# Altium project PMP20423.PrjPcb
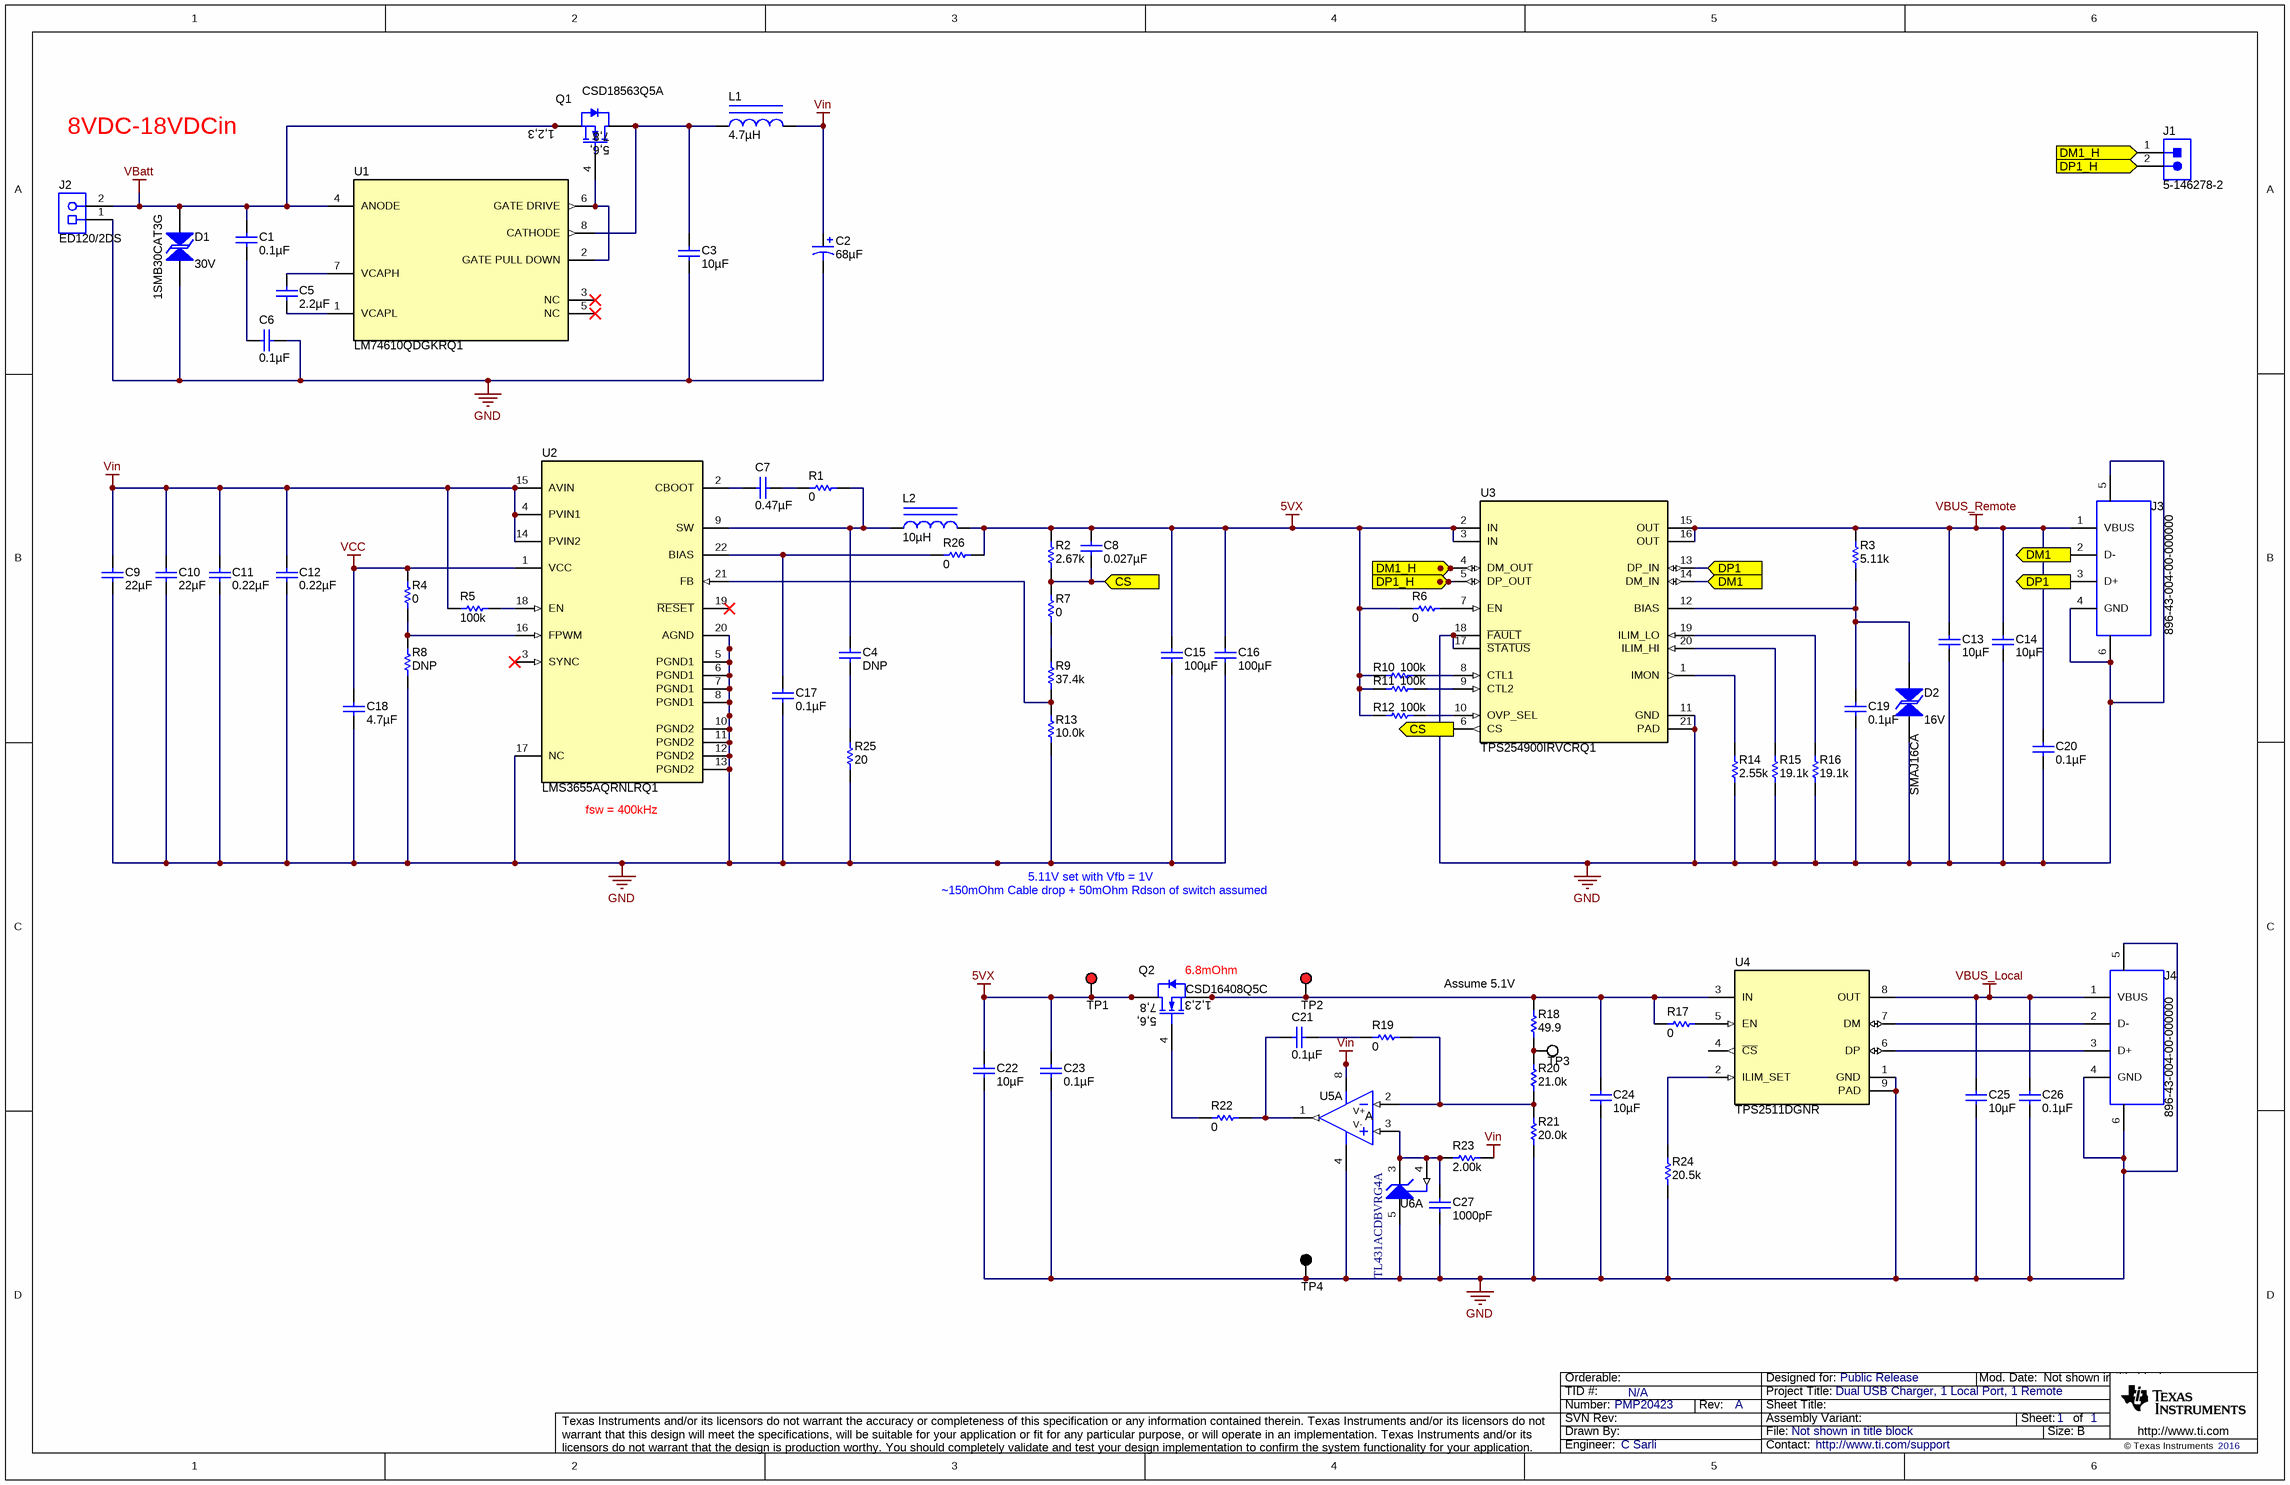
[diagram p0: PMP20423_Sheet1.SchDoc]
CopyrightYear: 2016; PCB_Layout: C Sarli; PCB_Rev: A; PRJ_Customer: Public Release; PRJ_Engineer: C Sarli; PRJ_Number: PMP20423; PRJ_Title: Dual USB Charger, 1 Local Port, 1 Remote; SCH_Rev: A; TechSupport: http://www.ti.com/support; TID: N/A
1 sheet, 73 parts. Net scope: flat (ports and power ports of the same name join across sheets).
Board file: PMP20423.PcbDoc

## Sheet PMP20423_Sheet1.SchDoc
size 431 x 279 mm; Date: Not shown in title block; ApprovedBy: Not shown in title block; CheckedBy: Not shown in title block; Author: Not shown in title block; CompanyName: Not shown in title block; Engineer: Not shown in title block; Organization: Not shown in title block; Address1: Not shown in title block; Address2: Not shown in title block; Address3: Not shown in title block; Address4: Not shown in title block; DocumentNumber: 1; Revision: Use project parameter SCH_Rev; SheetNumber: 1; SheetTotal: 1; PageSetup: Record=PageOptions¦CenterHorizontal=True¦CenterVertical=True¦PrintScale=1.00¦XCorrection=1.00¦YCorrection=1.00¦PrintKind=0¦BorderSize=5000000¦LeftOffset=0¦BottomOffset=0¦Orientation=2¦PaperLength=1000¦PaperWidth=1000¦Scale=100¦PaperSource=15¦PrintQuality=600¦MediaType=1¦DitherType=10¦PaperKind=Letter¦PrintScaleMode=1

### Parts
C1  ValueDisplayed: 0.1µF  [0402]  (hidden comment: C1005X7R1H104K050BB)
C2  ValueDisplayed: 68µF  [SM_RADIAL_D8]  (hidden comment: EEE-FK1V680XP)
C3  ValueDisplayed: 10µF  [1206_180]  (hidden comment: GRM31CR61H106KA12L)
C4  ValueDisplayed: DNP  [0402L]  (hidden comment: GRM155R71H331KA01D)
C5  ValueDisplayed: 2.2µF  [0603]  (hidden comment: GRM188R61A225KE34D)
C6  ValueDisplayed: 0.1µF  [0402]  (hidden comment: C1005X7R1H104K050BB)
C7  ValueDisplayed: 0.47µF  [0603L]  (hidden comment: GRM188R71E474KA12D)
C8  ValueDisplayed: 0.027µF  [0402L]  (hidden comment: GRM155R61C273KA01D)
C9  ValueDisplayed: 22µF  [1812_280L]  (hidden comment: C4532X7R1E226M250KC)
C10  ValueDisplayed: 22µF  [1812_280L]  (hidden comment: C4532X7R1E226M250KC)
C11  ValueDisplayed: 0.22µF  [0603L]  (hidden comment: C1608X7R1H224K080AB)
C12  ValueDisplayed: 0.22µF  [0603L]  (hidden comment: C1608X7R1H224K080AB)
C13  ValueDisplayed: 10µF  [0805_HV]  (hidden comment: GCM21BR70J106KE22L)
C14  ValueDisplayed: 10µF  [0805_HV]  (hidden comment: GCM21BR70J106KE22L)
C15  ValueDisplayed: 100µF  [1210_270L]  (hidden comment: GRM32ER61A107ME20L)
C16  ValueDisplayed: 100µF  [1210_270L]  (hidden comment: GRM32ER61A107ME20L)
C17  ValueDisplayed: 0.1µF  [0402L]  (hidden comment: C1005X7R1H104K050BB)
C18  ValueDisplayed: 4.7µF  [0603L]  (hidden comment: GRM188Z71C475KE21D)
C19  ValueDisplayed: 0.1µF  [0402L]  (hidden comment: C1005X7R1H104K050BB)
C20  ValueDisplayed: 0.1µF  [0402L]  (hidden comment: C1005X7R1H104K050BB)
C21  ValueDisplayed: 0.1µF  [0402L]  (hidden comment: C1005X7R1H104K050BB)
C22  ValueDisplayed: 10µF  [0805_HV]  (hidden comment: GRM21BR61C106KE15L)
C23  ValueDisplayed: 0.1µF  [0402L]  (hidden comment: C1005X7R1H104K050BB)
C24  ValueDisplayed: 10µF  [0805_HV]  (hidden comment: GRM21BR61C106KE15L)
C25  ValueDisplayed: 10µF  [0805_HV]  (hidden comment: GCM21BR70J106KE22L)
C26  ValueDisplayed: 0.1µF  [0402L]  (hidden comment: C1005X7R1H104K050BB)
C27  ValueDisplayed: 1000pF  [0402L]  (hidden comment: GRM155R61H102KA01D)
D1  1SMB30CAT3G  value 30V  [SMB-Bi]
D2  SMAJ16CA  value 16V  [SMA]
J1  5-146278-2  [TE_5-146278-2]
J2  ED120/2DS  [On-Shore_ED120_2DS]
J3  896-43-004-00-000000  [CONN_USB_896-43-004-00-000000]
J4  896-43-004-00-000000  [CONN_USB_896-43-004-00-000000]
L1  ValueDisplayed: 4.7µH  [XAL5030]  (hidden comment: XAL5030-472MEB)
L2  ValueDisplayed: 10µH  [MSS1278]  (hidden comment: MSS1278-103MLB)
Q1  CSD18563Q5A  [DQJ0008A]
Q2  CSD16408Q5C  [TRANS_NexFET_Q5C]
R1  ValueDisplayed: 0  [0402L]  (hidden comment: CRCW04020000Z0ED)
R2  ValueDisplayed: 2.67k  [0402L]  (hidden comment: CRCW04022K67FKED)
R3  ValueDisplayed: 5.11k  [0402L]  (hidden comment: CRCW04025K11FKED)
R4  ValueDisplayed: 0  [0402L]  (hidden comment: CRCW04020000Z0ED)
R5  ValueDisplayed: 100k  [0402L]  (hidden comment: CRCW0402100KJNED)
R6  ValueDisplayed: 0  [0402L]  (hidden comment: CRCW04020000Z0ED)
R7  ValueDisplayed: 0  [0402L]  (hidden comment: CRCW04020000Z0ED)
R8  ValueDisplayed: DNP  [0402L]  (hidden comment: CRCW04020000Z0ED)
R9  ValueDisplayed: 37.4k  [0402L]  (hidden comment: CRCW040237K4FKED)
R10  ValueDisplayed: 100k  [0402L]  (hidden comment: CRCW0402100KJNED)
R11  ValueDisplayed: 100k  [0402L]  (hidden comment: CRCW0402100KJNED)
R12  ValueDisplayed: 100k  [0402L]  (hidden comment: CRCW0402100KJNED)
R13  ValueDisplayed: 10.0k  [0402L]  (hidden comment: CRCW040210K0FKED)
R14  ValueDisplayed: 2.55k  [0402L]  (hidden comment: CRCW04022K55FKED)
R15  ValueDisplayed: 19.1k  [0402L]  (hidden comment: CRCW040219K1FKED)
R16  ValueDisplayed: 19.1k  [0402L]  (hidden comment: CRCW040219K1FKED)
R17  ValueDisplayed: 0  [0402L]  (hidden comment: CRCW04020000Z0ED)
R18  ValueDisplayed: 49.9  [0402L]  (hidden comment: CRCW040249R9FKED)
R19  ValueDisplayed: 0  [0402L]  (hidden comment: CRCW04020000Z0ED)
R20  ValueDisplayed: 21.0k  [0402L]  (hidden comment: CRCW040221K0FKED)
R21  ValueDisplayed: 20.0k  [0402L]  (hidden comment: CRCW040220K0FKED)
R22  ValueDisplayed: 0  [0402L]  (hidden comment: CRCW04020000Z0ED)
R23  ValueDisplayed: 2.00k  [0603L]  (hidden comment: CRCW06032K00FKEA)
R24  ValueDisplayed: 20.5k  [0402L]  (hidden comment: CRCW040220K5FKED)
R25  ValueDisplayed: 20  [0603]  (hidden comment: CRCW060320R0JNEA)
R26  ValueDisplayed: 0  [0402L]  (hidden comment: CRCW04020000Z0ED)
TP1  5000  [Keystone5000]  (value not drawn)
TP2  5000  [Keystone5000]  (value not drawn)
TP3  5002  [Keystone5002]  (value not drawn)
TP4  5001  [Keystone5001]  (value not drawn)
U1  LM74610QDGKRQ1  [DGK0008A_N]
U2  LMS3655AQRNLRQ1  [RNL0022A_NV]
U3  TPS254900IRVCRQ1  [RVC0020A]
U4  TPS2511DGNR  [DGN0008E_N]
U5  LM358AD  [D0008A_N]  (value not drawn)  (part A of 2)
U6  TL431ACDBVRG4A  [DBV0005A_N]  (part A of 2)

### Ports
CS, CS (in), DM1, DM1_H, DP1, DP1_H

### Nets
5VX: C8.1 C15.1 C16.1 C22.1 C23.1 L2.2 Q2.5(D) Q2.6(D) Q2.7(D) Q2.8(D) Q2.10(D) R2.2 R6.2 R10.2 R11.2 R12.2 R26.1 TP1.1 U3.2(IN) U3.3(IN)
GND: C2.2(-) C3.2 C6.2 C9.2 C10.2 C11.2 C12.2 C13.2 C14.2 C15.2 C16.2 C17.1 C18.2 C19.2 C20.2 C22.2 C23.2 C24.2 C25.2 C26.2 C27.2 D1.1 D2.1 J2.1 J3.4(GND) J3.5(Shield) J3.6(Shield) J4.4(GND) J4.5(Shield) J4.6(Shield) R8.1 R13.1 R14.1 R15.1 R16.1 R21.1 R24.1 R25.1 TP4.1 U2.5(PGND1) U2.6(PGND1) U2.7(PGND1) U2.8(PGND1) U2.10(PGND2) U2.11(PGND2) U2.12(PGND2) U2.13(PGND2) U2.17(NC) U2.20(AGND) U3.11(GND) U3.17(~{STATUS}) U3.18(~{FAULT}) U3.21(PAD) U4.1(GND) U4.9(PAD) U5.4(V-) U6.5(ANODE)
VBatt: C1.1 D1.2 J2.2 Q1.1(S) Q1.2(S) Q1.3(S) U1.4(ANODE)
VBUS_Local: C25.1 C26.1 J4.1(VBUS) U4.8(OUT)
VBUS_Remote: C13.1 C14.1 C20.1 J3.1(VBUS) R3.2 U3.15(OUT) U3.16(OUT)
VCC: C18.1 R4.2 U2.1(VCC)
Vin: C2.1(+) C9.1 C10.1 C11.1 C12.1 L1.2 R5.1 R23.2 U2.4(PVIN1) U2.14(PVIN2) U2.15(AVIN) U5.8(V+)
CS: C8.2 R2.1 R7.2 U3.6(CS) ; port CS
DM1: J3.2(D-) U3.14(DM_IN) ; port DM1
DM1_H: J1.1 U3.4(DM_OUT) ; port DM1_H
DP1: J3.3(D+) U3.13(DP_IN) ; port DP1
DP1_H: J1.2 U3.5(DP_OUT) ; port DP1_H
NetC1_2: C1.2 C6.1
NetC3_1: C3.1 L1.1 Q1.5(D) Q1.6(D) Q1.7(D) Q1.8(D) Q1.9(D) U1.8(CATHODE)
NetC4_1: C4.1 L2.1 R1.1 U2.9(SW)
NetC4_2: C4.2 R25.2
NetC5_1: C5.1 U1.7(VCAPH)
NetC5_2: C5.2 U1.1(VCAPL)
NetC7_1: C7.1 R1.2
NetC7_2: C7.2 U2.2(CBOOT)
NetC17_2: C17.2 R26.2 U2.22(BIAS)
NetC19_1: C19.1 D2.2 R3.1 U3.12(BIAS)
NetC21_1: C21.1 R22.1 U5.1(OUT)
NetC21_2: C21.2 R19.2
NetC24_1: C24.1 Q2.1(S) Q2.2(S) Q2.3(S) R17.2 R18.2 TP2.1 U4.3(IN)
NetC27_1: C27.1 R23.1 U5.3(IN+) U6.3(CATHODE) U6.4(REF)
NetJ4_2: J4.2(D-) U4.7(DM)
NetJ4_3: J4.3(D+) U4.6(DP)
NetQ1_4: Q1.4(G) U1.2(GATE_PULL_DOWN) U1.6(GATE_DRIVE)
NetQ2_4: Q2.4(G) R22.2
NetR4_1: R4.1 R8.2 U2.16(FPWM)
NetR5_2: R5.2 U2.18(EN)
NetR6_1: R6.1 U3.7(EN)
NetR7_1: R7.1 R9.2
NetR9_1: R9.1 R13.2 U2.21(FB)
NetR10_1: R10.1 U3.8(CTL1)
NetR11_1: R11.1 U3.9(CTL2)
NetR12_1: R12.1 U3.10(OVP_SEL)
NetR14_2: R14.2 U3.1(IMON)
NetR15_2: R15.2 U3.20(ILIM_HI)
NetR16_2: R16.2 U3.19(ILIM_LO)
NetR17_1: R17.1 U4.5(EN)
NetR18_1: R18.1 R20.2 TP3.1
NetR19_1: R19.1 R20.1 R21.2 U5.2(IN-)
NetR24_2: R24.2 U4.2(ILIM_SET)

Not connected (* = marked no-connect by the designer): U1 3(NC)* 5(NC)*; U2 3(SYNC)* 19(~{RESET})*; U4 4(~{CS})

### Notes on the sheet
- 8VDC-18VDCin
- (near U2) fsw = 400kHz
- 5.11V set with Vfb = 1V
- 50mOhm Cable drop + 50mOhm Rdson of switch assumed
- (near Q2) 6.8mOhm
- (near R18) Assume 5.1V

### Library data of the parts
C1 C6 = C1005X7R1H104K050BB: CAP, CERM, 0.1 µF, 50 V, +/- 10%, X7R, 0402; Manufacturer: TDK; Polarized: N; CompType: Capacitor; Value: 0.1uF; U/M: EA; Cap_F: 0.0000001; Tolerance_%: 10; ESR_ohm: 0.039064; Value1: 0.039064 ohm; VDC_V: 50; Value2: 50V; IRMS_A: 0.814669; TaMin_C: -55; TaMax_C: 125; SizeArea_mm2: 0.5; SizeAreaWB_mm2: 3; SizeX_mm: 1; SizeZ_mm: 0.6; AEC Category: Q200
C2 = EEE-FK1V680XP: CAP, AL, 68 µF, 35 V, +/- 20%, 0.34 ohm, AEC-Q200 Grade 2, SMD; Manufacturer: Panasonic; Polarized: Y; CompType: Capacitor; Value: 68uF; U/M: EA; Cap_F: 0.000068; Tolerance_%: 20; VDC_V: 35; Value2: 35V; ESR_ohm: 0.34; IRMS_A: 0.28; TaMin_C: -55; TaMax_C: 105; Cap_Case: D8; SizeAreaWB_mm2: 84.28; SizeArea_mm2: 51.48; SizeX_mm: 7.8; SizeY_mm: 6.6; SizeZ_mm: 7.7; AEC Category: Q200; AEC Grade: 2
C3 = GRM31CR61H106KA12L: CAP, CERM, 10 µF, 50 V, +/- 10%, X5R, 1206; Manufacturer: MuRata; Polarized: N; CompType: Capacitor; Value: 10uF; U/M: EA; Cap_F: 0.00001; Tolerance_%: 10; Value1: Unknown; VDC_V: 50; Value2: 50V; TaMin_C: -55; TaMax_C: 85; Cap_Case: 1206; SizeArea_mm2: 5.12; SizeAreaWB_mm2: 10.92; SizeX_mm: 3.2; SizeY_mm: 1.6; SizeZ_mm: 1.8; AEC Category: Q200
C4 = GRM155R71H331KA01D: CAP, CERM, 330 pF, 50 V,+/- 10%, X7R, 0402; Manufacturer: MuRata; Polarized: N; CompType: Capacitor; Value: 330pF; U/M: EA; Cap_F: 0.00000000033; Tolerance_%: 10; Value1: Unknown; VDC_V: 50; Value2: 50V; TaMin_C: -55; TaMax_C: 125; Cap_Case: 0402; SizeArea_mm2: 0.5; SizeAreaWB_mm2: 3; SizeX_mm: 1; SizeZ_mm: 0.6; AEC Category: Q200; Green_Lifecycle: Active; Green_REACh: Passed
C5 = GRM188R61A225KE34D: CAP, CERM, 2.2 µF, 10 V, +/- 10%, X5R, 0603; Manufacturer: MuRata; Polarized: N; CompType: Capacitor; Value: 2.2uF; U/M: EA; Cap_F: 0.0000022; Tolerance_%: 10; Value1: Unknown; Value2: 10V; TaMin_C: -55; TaMax_C: 85; SizeArea_mm2: 1.28; SizeAreaWB_mm2: 4.68; SizeX_mm: 1.6; SizeY_mm: 0.8; SizeZ_mm: 1; AEC Category: Q200
C7 = GRM188R71E474KA12D: CAP, CERM, 0.47 µF, 25 V,+/- 10%, X7R, 0603; Manufacturer: MuRata; Polarized: N; CompType: Capacitor; Value: 0.47uF; U/M: EA; Cap_F: 0.00000047; Tolerance_%: 10; Value1: Unknown; VDC_V: 25; Value2: 25V; TaMin_C: -55; TaMax_C: 125; Cap_Case: 0603; SizeArea_mm2: 1.28; SizeAreaWB_mm2: 4.68; SizeX_mm: 1.6; SizeY_mm: 0.8; SizeZ_mm: 1; AEC Category: Q200; Green_Lifecycle: Active; Green_REACh: Passed
C8 = GRM155R61C273KA01D: CAP, CERM, 0.027 µF, 16 V,+/- 10%, X5R, 0402; Manufacturer: MuRata; Polarized: N; CompType: Capacitor; Value: 0.027uF; U/M: EA; Cap_F: 0.000000027; Tolerance_%: 10; Value1: Unknown; VDC_V: 16; Value2: 16V; TaMin_C: -55; TaMax_C: 85; Cap_Case: 0402; SizeArea_mm2: 0.5; SizeAreaWB_mm2: 3; SizeX_mm: 1; SizeZ_mm: 0.6; AEC Category: Q200
C9 C10 = C4532X7R1E226M250KC: CAP, CERM, 22 µF, 25 V,+/- 20%, X7R, 1812; Manufacturer: TDK; Polarized: N; CompType: Capacitor; Value: 22uF; U/M: EA; Cap_F: 0.000022; Tolerance_%: 20; ESR_ohm: 0.002434; Value1: 0.002434 ohm; VDC_V: 25; Value2: 25V; IRMS_A: 4.91649; TaMin_C: -55; TaMax_C: 125; Cap_Case: 1812; SizeArea_mm2: 14.4; SizeAreaWB_mm2: 23.1; SizeX_mm: 4.5; SizeY_mm: 3.2; SizeZ_mm: 2.8; AEC Category: Q200; Green_Lifecycle: Active; Green_REACh: Passed
C11 C12 = C1608X7R1H224K080AB: CAP, CERM, 0.22 µF, 50 V,+/- 10%, X7R, 0603; Manufacturer: TDK; Polarized: N; CompType: Capacitor; Value: 0.22uF; U/M: EA; Cap_F: 0.00000022; Tolerance_%: 10; ESR_ohm: 0.021699; Value1: 0.021699 ohm; VDC_V: 50; Value2: 50V; IRMS_A: 1.12496; TaMin_C: -55; TaMax_C: 125; Cap_Case: 0603; SizeArea_mm2: 1.28; SizeAreaWB_mm2: 4.68; SizeX_mm: 1.6; SizeY_mm: 0.8; SizeZ_mm: 1; AEC Category: Q200; Green_Lifecycle: Active; Green_REACh: Passed
C13 C14 C25 = GCM21BR70J106KE22L: CAP, CERM, 10 µF, 6.3 V, +/- 10%, X7R, 0805; Manufacturer: MuRata; Polarized: N; CompType: Capacitor; Value: 10uF; U/M: EA; Cap_F: 0.00001; Tolerance_%: 10; Value1: Unknown; VDC_V: 6.3; Value2: 6.3V; TaMin_C: -55; TaMax_C: 125; Cap_Case: 0805; SizeArea_mm2: 2.5; SizeAreaWB_mm2: 6.75; SizeX_mm: 2; SizeY_mm: 1.25; SizeZ_mm: 1.45; AEC Category: Q200
C15 C16 = GRM32ER61A107ME20L: CAP, CERM, 100 µF, 10 V,+/- 20%, X5R, 1210; Manufacturer: MuRata; Polarized: N; CompType: Capacitor; Value: 100uF; U/M: EA; Cap_F: 0.0001; Tolerance_%: 20; Value1: Unknown; VDC_V: 10; Value2: 10V; TaMin_C: -55; TaMax_C: 85; Cap_Case: 1210; SizeArea_mm2: 8; SizeAreaWB_mm2: 14.7; SizeX_mm: 3.2; SizeY_mm: 2.5; SizeZ_mm: 2.7; AEC Category: Q200
C17 C19-C21 C23 C26 = C1005X7R1H104K050BB: CAP, CERM, 0.1 µF, 50 V, +/- 10%, X7R, 0402; Manufacturer: TDK; Polarized: N; CompType: Capacitor; Value: 0.1uF; U/M: EA; Cap_F: 0.0000001; Tolerance_%: 10; ESR_ohm: 0.039064; Value1: 0.039064 ohm; VDC_V: 50; Value2: 50V; IRMS_A: 0.814669; TaMin_C: -55; TaMax_C: 125; Cap_Case: 0402; SizeArea_mm2: 0.5; SizeAreaWB_mm2: 3; SizeX_mm: 1; SizeZ_mm: 0.6; AEC Category: Q200
C18 = GRM188Z71C475KE21D: CAP, CERM, 4.7 µF, 16 V,+/- 10%, X7R, 0603; Manufacturer: MuRata; Polarized: N; CompType: Capacitor; Value: 4.7uF; U/M: EA; Cap_F: 0.0000047; Tolerance_%: 10; Value1: Unknown; VDC_V: 16; Value2: 16V; TaMin_C: -55; TaMax_C: 125; Cap_Case: 0603; SizeArea_mm2: 1.28; SizeAreaWB_mm2: 4.68; SizeX_mm: 1.6; SizeY_mm: 0.8; SizeZ_mm: 1; AEC Category: Q200
C22 C24 = GRM21BR61C106KE15L: CAP, CERM, 10 µF, 16 V,+/- 10%, X5R, 0805; Manufacturer: MuRata; Polarized: N; CompType: Capacitor; Value: 10uF; U/M: EA; Cap_F: 0.00001; Tolerance_%: 10; ESR_ohm: 0.008; Value1: 0.008 ohm; VDC_V: 16; Value2: 16V; TaMin_C: -55; TaMax_C: 85; Cap_Case: 0805; SizeArea_mm2: 2.5; SizeAreaWB_mm2: 6.75; SizeX_mm: 2; SizeY_mm: 1.25; SizeZ_mm: 1.45; AEC Category: Q200; Green_Lifecycle: Active; Green_REACh: Passed
C27 = GRM155R61H102KA01D: CAP, CERM, 1000 pF, 50 V, +/- 10%, X5R, 0402; Manufacturer: MuRata; Polarized: N; CompType: Capacitor; Value: 1000pF; U/M: EA; Cap_F: 0.000000001; Tolerance_%: 10; Value1: Unknown; VDC_V: 50; Value2: 50V; TaMin_C: -55; TaMax_C: 85; Cap_Case: 0402; SizeArea_mm2: 0.5; SizeAreaWB_mm2: 3; SizeX_mm: 1; SizeZ_mm: 0.6; AEC Category: Q200
D1 = 1SMB30CAT3G: Diode, TVS, Bi, 30 V, 600 W, SMB; Manufacturer: ON Semiconductor; U/M: EA; Power_W: 600; Vr_V: 30; Value1: 600W; AEC Category: Q101
D2 = SMAJ16CA: Diode, TVS, Bi, 16 V, 400 W, SMA; Manufacturer: Littelfuse; U/M: EA; Power_W: 400; Vr_V: 16; Value1: 400W; RJA_CperW: 120; SizeAreaWB_mm2: 37.3428; SizeArea_mm2: 16.3228; SizeX_mm: 5.59; SizeY_mm: 2.92; SizeZ_mm: 2.87; AEC Category: Q101
J1 = 5-146278-2: Header, 100mil, 2x1, Tin, TH; Manufacturer: TE Connectivity; SymbolCreator: a0412235
J2 = ED120/2DS: Terminal Block, 5.08 mm, 2x1, Brass, TH; Manufacturer: On-Shore Technology; SymbolCreator: a0412235; Pitch_mm: 5.08; Gender: Female; Shrouded: N; Row_Count: 1; Current_A: 15; Voltage_V: 300; Cert_CULUS: Y
J3 J4 = 896-43-004-00-000000: Connector, Receptacle, USB TYPE A, R/A, Top Mount SMT; Manufacturer: Mill-Max; SymbolCreator: a0412235; Pitch_mm: 2; Gender: Female; Shrouded: N; Row_Count: 1; ContactFinish: Gold; Voltage_V: 30
L1 = XAL5030-472MEB: Inductor, Shielded, Composite, 4.7 µH, 5.9 A, 0.04 ohm, SMD; Manufacturer: Coilcraft; Value: 4.7uH; Ind_H: 4.7E-6; Imax_A: 5.9; Irms: 5.9A @ 40C rise; Isat: 6.7A @ 30% inductance drop; DCR_ohm: 0.04; Value2: 5.9A; SizeAreaWB_mm2: 54.4544; SizeArea_mm2: 28.9344; SizeX_mm: 5.28; SizeY_mm: 5.48; SizeZ_mm: 3.1; AEC Category: Q200
L2 = MSS1278-103MLB: Inductor, Shielded Drum Core, Ferrite, 10 µH, 5.7 A, 0.02 ohm, SMD; Manufacturer: Coilcraft; Value: 10uH; Ind_H: 10.0E-6; Imax_A: 5.7; Irms: 5.7A @ 40C rise; Isat: 11.2A @ 30% inductance drop; DCR_ohm: 0.02; Value2: 5.7A; SizeAreaWB_mm2: 204.49; SizeArea_mm2: 151.29; SizeX_mm: 12.3; SizeZ_mm: 8.05; AEC Category: Q200; Green_Lifecycle: Not Set; Green_REACh: Incomplete
Q1 = CSD18563Q5A: MOSFET, N-CH, 60 V, 15 A, DQJ0008A (VSONP-8); Manufacturer: Texas Instruments; Alternate Manufacturer: None; U/M: EA; ChType: N; Value: 60V; VdsMax_V: 60; Value1: 0.0086 ohm; Rdson45_ohm: 0.0086; Value2: 15 nC; QgTyp_nC: 15; Vgs_V: 20; SizeAreaWB_mm2: 55.2; SizeArea_mm2: 29.4; SizeX_mm: 6; SizeY_mm: 4.9; SizeZ_mm: 1.1; AEC Category: Q101
Q2 = CSD16408Q5C: MOSFET, N-CH, 25 V, 113 A, DualCool SON 5x6mm; Manufacturer: Texas Instruments; Alternate Manufacturer: None; U/M: EA; ChType: N; Value: 25V; VdsMax_V: 25; Value1: 0.0054 ohm; Rdson45_ohm: 0.0054; Value2: 6.7 nC; QgTyp_nC: 6.7; Vgs_V: 16; IdsMax_A: 113; SizeAreaWB_mm2: 56; SizeArea_mm2: 30; SizeX_mm: 6; SizeY_mm: 5; SizeZ_mm: 1; AEC Category: Q101
R1 R4 R7 R8 R26 = CRCW04020000Z0ED: RES, 0, 5%, 0.063 W, 0402; Manufacturer: Vishay-Dale; CompType: Resistor; Value: 0; Value_Code: 0000; Tolerance_%: 5; Power_W: 0.063; Value2: 0.063W; VDC_V: 50; TempCo: 200 ppm/C; SizeArea_mm2: 0.5; SizeX_mm: 1; SizeZ_mm: 0.6; EIA_Code: E24; U/M: EA; AEC Category: Q200; Green_Lifecycle: Active; Green_REACh: Passed
R2 = CRCW04022K67FKED: RES, 2.67 k, 1%, 0.063 W, 0402; Manufacturer: Vishay-Dale; CompType: Resistor; Value: 2.67k; Res_ohm: 2670; Value_Code: 2k67; Tolerance_%: 1; Power_W: 0.063; Value2: 0.063W; VDC_V: 50; TempCo: 100 ppm/C; SizeArea_mm2: 0.5; SizeZ_mm: 0.6; EIA_Code: E96; U/M: EA; AEC Category: Q200
R3 = CRCW04025K11FKED: RES, 5.11 k, 1%, 0.063 W, 0402; Manufacturer: Vishay-Dale; CompType: Resistor; Value: 5.11k; Res_ohm: 5110; Value_Code: 5k11; Tolerance_%: 1; Power_W: 0.063; Value2: 0.063W; VDC_V: 50; TempCo: 100 ppm/C; SizeArea_mm2: 0.5; SizeZ_mm: 0.6; EIA_Code: E96; U/M: EA; AEC Category: Q200
R5 = CRCW0402100KJNED: RES, 100 k, 5%, 0.063 W, 0402; Manufacturer: Vishay-Dale; CompType: Resistor; Value: 100k; Res_ohm: 100000; Tolerance_%: 5; Power_W: 0.063; Value2: 0.063W; VDC_V: 50; TempCo: 200 ppm/C; SizeArea_mm2: 0.5; SizeX_mm: 1; SizeZ_mm: 0.6; EIA_Code: E24; U/M: EA; AEC Category: Q200; Green_Lifecycle: Active; Green_REACh: Passed
R6 R17 R19 R22 = CRCW04020000Z0ED: RES, 0, 5%, 0.063 W, 0402; Manufacturer: Vishay-Dale; CompType: Resistor; Value: 0; Value_Code: 0000; Tolerance_%: 5; Power_W: 0.063; Value2: 0.063W; VDC_V: 50; TempCo: 200 ppm/C; SizeArea_mm2: 0.5; SizeX_mm: 1; SizeZ_mm: 0.6; EIA_Code: E24; U/M: EA; AEC Category: Q200
R9 = CRCW040237K4FKED: RES, 37.4 k, 1%, 0.063 W, 0402; Manufacturer: Vishay-Dale; CompType: Resistor; Value: 37.4k; Res_ohm: 37400; Value_Code: 37k4; Tolerance_%: 1; Power_W: 0.063; Value2: 0.063W; VDC_V: 50; TempCo: 100 ppm/C; SizeArea_mm2: 0.5; SizeZ_mm: 0.6; EIA_Code: E96; U/M: EA; AEC Category: Q200; Green_Lifecycle: Active; Green_REACh: Passed
R10-R12 = CRCW0402100KJNED: RES, 100 k, 5%, 0.063 W, 0402; Manufacturer: Vishay-Dale; CompType: Resistor; Value: 100k; Res_ohm: 100000; Tolerance_%: 5; Power_W: 0.063; Value2: 0.063W; VDC_V: 50; TempCo: 200 ppm/C; SizeArea_mm2: 0.5; SizeX_mm: 1; SizeZ_mm: 0.6; EIA_Code: E24; U/M: EA; AEC Category: Q200
R13 = CRCW040210K0FKED: RES, 10.0 k, 1%, 0.063 W, 0402; Manufacturer: Vishay-Dale; CompType: Resistor; Value: 10.0k; Res_ohm: 10000; Value_Code: 10k0; Tolerance_%: 1; Power_W: 0.063; Value2: 0.063W; VDC_V: 50; TempCo: 100 ppm/C; SizeArea_mm2: 0.5; SizeZ_mm: 0.6; EIA_Code: E96; U/M: EA; AEC Category: Q200; Green_Lifecycle: Active; Green_REACh: Passed
R14 = CRCW04022K55FKED: RES, 2.55 k, 1%, 0.063 W, 0402; Manufacturer: Vishay-Dale; CompType: Resistor; Value: 2.55k; Res_ohm: 2550; Value_Code: 2k55; Tolerance_%: 1; Power_W: 0.063; Value2: 0.063W; VDC_V: 50; TempCo: 100 ppm/C; SizeArea_mm2: 0.5; SizeZ_mm: 0.6; EIA_Code: E96; U/M: EA; AEC Category: Q200
R15 R16 = CRCW040219K1FKED: RES, 19.1 k, 1%, 0.063 W, 0402; Manufacturer: Vishay-Dale; CompType: Resistor; Value: 19.1k; Res_ohm: 19100; Value_Code: 19k1; Tolerance_%: 1; Power_W: 0.063; Value2: 0.063W; VDC_V: 50; TempCo: 100 ppm/C; SizeArea_mm2: 0.5; SizeZ_mm: 0.6; EIA_Code: E96; U/M: EA; AEC Category: Q200
R18 = CRCW040249R9FKED: RES, 49.9, 1%, 0.063 W, 0402; Manufacturer: Vishay-Dale; CompType: Resistor; Value: 49.9; Value_Code: 49R9; Tolerance_%: 1; Power_W: 0.063; Value2: 0.063W; VDC_V: 50; TempCo: 100 ppm/C; SizeArea_mm2: 0.5; SizeZ_mm: 0.6; EIA_Code: E96; U/M: EA; AEC Category: Q200
R20 = CRCW040221K0FKED: RES, 21.0 k, 1%, 0.063 W, 0402; Manufacturer: Vishay-Dale; CompType: Resistor; Value: 21.0k; Res_ohm: 21000; Value_Code: 21k0; Tolerance_%: 1; Power_W: 0.063; Value2: 0.063W; VDC_V: 50; TempCo: 100 ppm/C; SizeArea_mm2: 0.5; SizeZ_mm: 0.6; EIA_Code: E96; U/M: EA; AEC Category: Q200
R21 = CRCW040220K0FKED: RES, 20.0 k, 1%, 0.063 W, 0402; Manufacturer: Vishay-Dale; CompType: Resistor; Value: 20.0k; Res_ohm: 20000; Value_Code: 20k0; Tolerance_%: 1; Power_W: 0.063; Value2: 0.063W; VDC_V: 50; TempCo: 100 ppm/C; SizeArea_mm2: 0.5; SizeZ_mm: 0.6; EIA_Code: E96; U/M: EA; AEC Category: Q200
R23 = CRCW06032K00FKEA: RES, 2.00 k, 1%, 0.1 W, 0603; Manufacturer: Vishay-Dale; CompType: Resistor; Value: 2.00k; Res_ohm: 2000; Value_Code: 2k00; Tolerance_%: 1; Power_W: 0.1; Value2: 0.1W; VDC_V: 75; TempCo: 100 ppm/C; SizeArea_mm2: 1.28; SizeX_mm: 1.6; SizeY_mm: 0.8; EIA_Code: E96; U/M: EA; AEC Category: Q200
R24 = CRCW040220K5FKED: RES, 20.5 k, 1%, 0.063 W, 0402; Manufacturer: Vishay-Dale; CompType: Resistor; Value: 20.5k; Res_ohm: 20500; Value_Code: 20k5; Tolerance_%: 1; Power_W: 0.063; Value2: 0.063W; VDC_V: 50; TempCo: 100 ppm/C; SizeArea_mm2: 0.5; SizeZ_mm: 0.6; EIA_Code: E96; U/M: EA; AEC Category: Q200
R25 = CRCW060320R0JNEA: RES, 20, 5%, 0.1 W, 0603; Manufacturer: Vishay-Dale; CompType: Resistor; Value: 20; Value_Code: 20R0; Tolerance_%: 5; Power_W: 0.1; Value2: 0.1W; VDC_V: 75; TempCo: 200 ppm/C; SizeArea_mm2: 1.28; SizeX_mm: 1.6; SizeY_mm: 0.8; SizeZ_mm: 1; EIA_Code: E24; U/M: EA; AEC Category: Q200
TP1 TP2 = 5000: Test Point, Miniature, Red, TH; Manufacturer: Keystone; CompType: Test Point Loop; ContactFinish: Silver
TP3 = 5002: Test Point, Miniature, White, TH; Manufacturer: Keystone; CompType: Test Point Loop; ContactFinish: Silver
TP4 = 5001: Test Point, Miniature, Black, TH; Manufacturer: Keystone; CompType: Test Point Loop; ContactFinish: Silver
U1 = LM74610QDGKRQ1: Smart Diode Controller, DGK0008A; Manufacturer: Texas Instruments; SymbolCreator: Altium; SizeArea_mm2: 15.655; SizeAreaWB_mm2: 35.955; SizeX_mm: 5.05; SizeY_mm: 3.1; SizeZ_mm: 1.1; CompType: IC; U/M: EA
U2 = LMS3655AQRNLRQ1: 5.5A Synchronous Buck Regulator for Automotive Applications, RNL0022A (VQFN-HR-22); Alternate PartNumber: LMS3655AQRNLTQ1; Manufacturer: Texas Instruments; SymbolCreator: Altium; SizeArea_mm2: 20; SizeAreaWB_mm2: 42; SizeX_mm: 4; SizeY_mm: 5; SizeZ_mm: 0.9; CompType: IC; U/M: EA
U3 = TPS254900IRVCRQ1: Automotive USB Charging Port Controller and Power Switch with Short to BAT protection, RVC0020A; Alternate PartNumber: TPS254900IRVCTQ1; Manufacturer: Texas Instruments; SymbolCreator: Altium; SizeArea_mm2: 12; SizeAreaWB_mm2: 20; SizeX_mm: 3; SizeY_mm: 4; SizeZ_mm: 0.8; CompType: IC; U/M: EA
U4 = TPS2511DGNR: USMB Dedicated Charging Port Controller and Current Limiting Power Switch, DGN0008E; Manufacturer: Texas Instruments; SymbolCreator: a0411947; SizeArea_mm2: 14.64; SizeAreaWB_mm2: 23.52; SizeX_mm: 4.88; SizeY_mm: 3; SizeZ_mm: 1.1; CompType: IC; U/M: EA
U5 = LM358AD: Dual Low Power Op Amp, D0008A; Manufacturer: Texas Instruments; CompType: OpAmp IC
U6 = TL431ACDBVRG4: Adjustable Precision Shunt Regulator, 34 ppm / degC, 100 mA, 0 to 70 degC, 5-pin SOT-23 (DBV), Green (RoHS & no Sb/Br); Manufacturer: Texas Instruments; Alternate PartNumber: Equivalent; Iout/Iz(Max)(mA): 100; Min Iz for Regulation(uA): 600; Rating: Catalog; SubFamily: Shunt Voltage Reference; Temp Coeff(Max)(ppm/ degree C): 92; Temp Coeff(Typ)(ppm/ degree C): 34; VO Adj(Max)(V): 36; VO Adj(Min)(V): 2.495

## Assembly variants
001: not fitted C4 R8 R25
